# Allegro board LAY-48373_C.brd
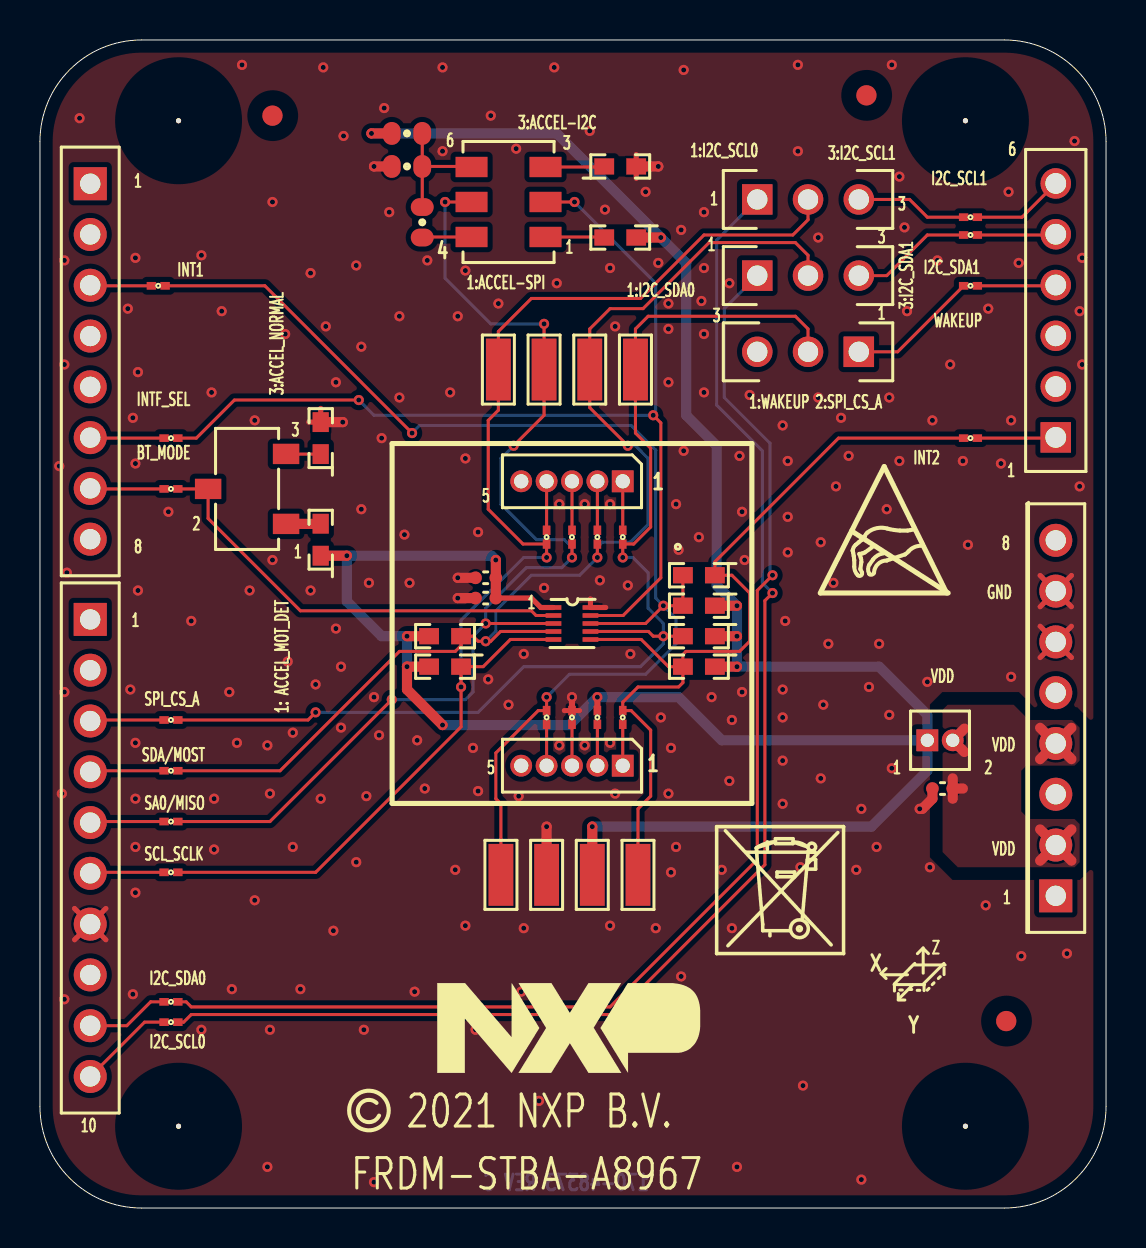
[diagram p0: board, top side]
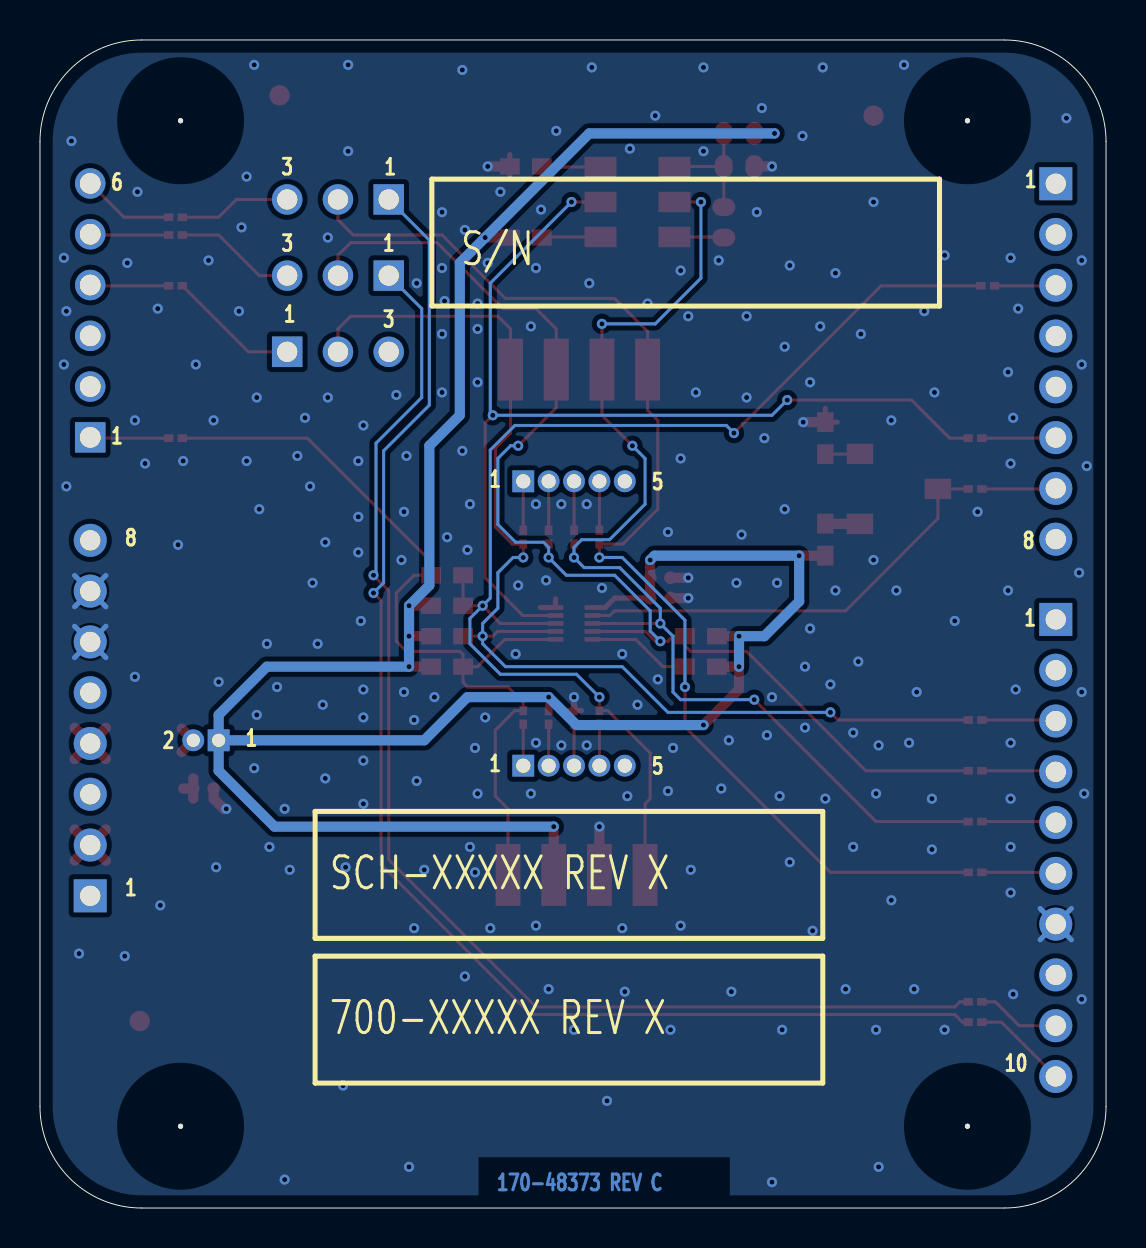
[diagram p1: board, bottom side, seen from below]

Outline 53.34 x 58.42 mm; copper layers: TOP, BOTTOM. Coordinates in mm from the lower left corner of the outline.
Outline path: 0,53.34 0,5.08 arc(1.49,1.49) 5.08,0 48.26,0 arc(51.85,1.49) 53.34,5.08 53.34,53.34 arc(51.85,56.93) 48.26,58.42 5.08,58.42 arc(1.49,56.93) 0,53.34

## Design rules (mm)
constraint set DEFAULT: min track width 0.152

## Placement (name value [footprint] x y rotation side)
C4  0.1UF  [CC0402_25]  22.3 30.51 180 top
C5  1.0UF  [CC0402_25]  22.3 31.52 180 top
C16  2.2UF  [CC0402_25]  45.16 20.98 180 top
GND  0805  [TESTPOINT_122X049MIL]  25.35 16.66 90 top
INT1  0805  [TESTPOINT_122X049MIL]  23.06 16.66 90 top
INT2  0805  [TESTPOINT_122X049MIL]  29.92 16.66 90 top
J1  HDR 1X5  [HDR1X5_50_TH]  29.16 36.35 0 top
J2  HDR 1X5  [HDR1X5_50_TH]  29.16 22.12 0 top
J3  SKT_1X8  [CON_SKT1X8_TH]  2.51 51.23 0 top
J4  SKT_1X6  [CON_SKT1X6_TH]  50.83 38.54 180 top
J5  SKT_1X10  [CON_SKT1X10_TH]  2.51 29.44 0 top
J6  SKT_1X8  [CON_SKT1X8_TH]  50.83 15.61 180 top
J7  HDR TH 1X3  [HDR103]  35.89 46.63 90 top
J8  HDR TH 1X3  [HDR103]  35.89 50.44 90 top
J9  HDR TH 1X3  [HDR103]  40.97 42.82 270 top
J10  HDR 1X2  [HDR1X2_1P27_TH]  44.4 23.39 180 top
NOREF  -  [unnamed]  6.93 54.38 0 top
NOREF#2  -  [#2]  46.48 0 90 top
NOREF#3  -  [#2]  -125.2 -12.08 90 top
NOREF#4  -  [#2]  30.55 15.66 90 top
NOREF#5  -  [#2]  23.69 15.66 90 top
NOREF#6  -  [#2]  -142.22 4.41 0 top
NOREF#7  -  [#2]  25.85 40.94 90 top
NOREF#8  -  [unnamed]  41.35 55.65 180 top
NOREF#9  -  [#2]  -125.2 3.16 90 top
NOREF#10  -  [#2]  33.86 12.73 0 top
NOREF#11  -  [#2]  -131.4 5.34 0 top
NOREF#12  -  [#2]  -125.2 -1.92 90 top
NOREF#13  -  [#2]  16.46 4.85 0 top
NOREF#14  -  [#2]  -142.22 1.87 0 top
NOREF#15  -  [#2]  16.71 35.2 0 top
NOREF#16  -  [#2]  -125.2 4.41 0 top
NOREF#17  -  [#2]  -125.2 -8.29 0 top
NOREF#18  -  [#2]  -125.2 6.95 0 top
NOREF#19  -  [#2]  39.07 30.76 0 top
NOREF#20  -  [#2]  -142.22 -1.92 90 top
NOREF#21  -  [#2]  -134.38 2.34 0 top
NOREF#22  -  [#2]  -125.2 -13.37 0 top
NOREF#23  -  [#2]  -142.22 6.95 0 top
NOREF#24  -  [#2]  -25.42 -46.55 0 top
NOREF#25  -  [#2]  29.3 17.66 0 top
NOREF#26  -  [#2]  -431.98 245.39 0 top
NOREF#27  -  [#2]  24.6 42.94 0 top
NOREF#28  -  [#2]  27.01 15.66 90 top
NOREF#29  -  [unnamed]  46.3 54.38 0 top
NOREF#30  -  [#2]  16.71 20.98 90 top
NOREF#31  -  [#2]  -142.22 3.16 90 top
NOREF#32  -  [#2]  -125.2 5.7 90 top
NOREF#33  -  [#2]  -142.22 5.7 90 top
NOREF#34  -  [#2]  -142.22 -14.62 90 top
NOREF#35  -  [unnamed]  6.93 4.09 0 top
NOREF#36  -  [#2]  -142.22 -9.54 90 top
NOREF#37  -  [#2]  -125.2 -5.75 0 top
NOREF#38  -  [#2]  16.71 20.98 0 top
NOREF#39  -  [#2]  27.01 15.66 0 top
NOREF#40  -  [#2]  -125.2 -9.54 90 top
NOREF#41  -  [#2]  52.79 55.63 0 top
NOREF#42  -  [#2]  22.44 17.66 0 top
NOREF#43  -  [unnamed]  11.63 54.64 180 top
NOREF#44  -  [#2]  22.31 42.94 0 top
NOREF#45  -  [#2]  44.05 7.77 0 top
NOREF#46  -  [#2]  -142.22 0.62 90 top
NOREF#47  -  [#2]  -132.38 2.56 90 top
NOREF#48  -  [#2]  23.56 40.94 90 top
NOREF#49  -  [#2]  -125.2 -4.46 90 top
NOREF#50  -  [#2]  -142.22 -10.83 0 top
NOREF#51  -  [#2]  -133.38 2.56 90 top
NOREF#52  -  [#2]  -131.38 2.34 90 top
NOREF#53  -  [#2]  -142.22 -7 90 top
NOREF#54  -  [#2]  -142.22 -8.29 0 top
NOREF#55  -  [#2]  -131.61 2.84 90 top
NOREF#56  -  [#2]  -125.2 1.87 0 top
NOREF#57  -  [#2]  25.97 15.66 90 top
NOREF#58  -  [#2]  30.42 40.94 90 top
NOREF#59  -  [unnamed]  46.3 4.09 0 top
NOREF#60  -  [#2]  24.72 17.66 0 top
NOREF#61  -  [#2]  17.62 38.24 0 top
NOREF#62  -  [unnamed]  48.35 9.35 180 top
NOREF#63  -  [#2]  27.89 22.12 0 top
NOREF#64  -  [#2]  -125.2 -0.67 0 top
NOREF#65  -  [#2]  -131.61 2.84 90 top
NOREF#66  -  [#2]  -142.22 -4.46 90 top
NOREF#67  -  [#2]  -134.16 2.84 0 top
NOREF#68  -  [#2]  -125.2 -3.21 0 top
NOREF#69  -  [#2]  -142.22 -12.08 90 top
NOREF#70  -  [#2]  -142.22 -0.67 0 top
NOREF#71  -  [#2]  16.71 35.2 90 top
NOREF#72  -  [#2]  44.4 23.39 0 top
NOREF#73  -  [#2]  -142.22 -3.21 0 top
NOREF#74  -  [#2]  -142.22 -5.75 0 top
NOREF#75  -  [#2]  17.62 20.24 90 top
NOREF#76  -  [#2]  -125.2 -10.83 0 top
NOREF#77  -  [#2]  29.17 42.94 0 top
NOREF#78  -  [#2]  6.45 2.61 0 top
NOREF#79  -  [#2]  -133.38 2.56 0 top
NOREF#80  -  [#2]  -458.69 -278.74 0 top
NOREF#81  -  [#2]  26.88 42.94 0 top
NOREF#82  -  [#2]  27.89 36.35 0 top
NOREF#83  -  [#2]  -125.2 -14.62 90 top
NOREF#84  -  [#2]  0 52.62 0 top
NOREF#85  -  [#2]  -125.2 -7 90 top
NOREF#86  -  [#2]  28.13 40.94 90 top
NOREF#87  -  [#2]  43.74 24.68 0 top
NOREF#88  -  [#2]  -131.61 2.84 90 top
NOREF#89  -  [#2]  19.89 6.76 0 top
NOREF#90  -  [#2]  -125.2 0.62 90 top
NOREF#91  -  [#2]  -142.22 -13.37 0 top
NOREF#92  -  [#2]  39.57 6.25 180 bottom
NOREF#93  -  [#2]  39.57 13.49 180 bottom
NOREF#94  -  [#2]  33.73 45.11 180 bottom
R1  4.7K  [RC0603]  20.27 27.08 180 top
R3  4.7K  [RC0603]  20.27 28.6 180 top
R4  10K  [RC0603]  32.97 28.6 180 top
R6  10K  [RC0603]  32.97 30.12 180 top
R8  100K  [RC0603_OV]  18.36 52.1 180 top
R9  10K  [RC0603]  32.97 27.08 180 top
R10  0  [RC0603]  32.97 31.65 180 top
R12  100K  [RC0603_OV]  18.36 53.75 0 top
R19  10K  [RC0603]  14.05 38.51 90 top
R20  10K  [RC0603]  14.05 33.43 90 top
R21  10K  [RC0603]  29.03 52.1 0 top
R24  10K  [RC0603]  29.03 48.54 180 top
R28  0  [RC0603_OV]  19.13 49.3 90 top
SA0_MISO  0805  [TESTPOINT_122X049MIL]  25.22 41.94 90 top
SCL1_SCLK  0805  [TESTPOINT_122X049MIL]  22.94 41.94 90 top
SDA1_MOSI  0805  [TESTPOINT_122X049MIL]  27.51 41.94 90 top
SH1  0  [SH0201]  25.35 24.54 90 top
SH4  0  [SH0201]  27.89 24.54 90 top
SH5  0  [SH0201]  25.35 33.55 270 top
SH8  0  [SH0201]  29.16 33.55 270 top
SH9  0  [SH0201]  27.89 33.55 270 top
SH10  0  [SH0201]  29.16 24.54 90 top
SH11  0  [SH0201]  26.62 33.55 270 top
SH20  0  [SH0201]  26.62 24.54 90 top
SH21  0  [SH0201]  46.56 49.56 0 top
SH22  0  [SH0201]  5.92 46.13 0 top
SH23  0  [SH0201]  46.56 48.67 0 top
SH27  0  [SH0201]  46.56 38.51 0 top
SH30  0  [SH0201]  6.55 24.41 0 top
SH31  0  [SH0201]  6.55 21.87 0 top
SH32  0  [SH0201]  6.55 19.33 0 top
SH33  0  [SH0201]  6.55 16.79 0 top
SH34  0  [SH0201]  6.55 10.31 0 top
SH35  0  [SH0201]  6.55 9.3 0 top
SH37  0  [SH0201]  6.55 38.51 0 top
SH38  0  [SH0201]  6.55 35.97 0 top
SH39  0  [SH0201]  46.56 46.13 0 top
SPI_CS_A  0805  [TESTPOINT_122X049MIL]  29.79 41.94 90 top
SW1  CAS-120TB  [SW3_1P75_3X6]  10.36 35.97 90 top
SW2  CAS-220TA  [SW6_1P75_4X5]  23.44 50.32 90 top
U2  FXLS8967AFR3  [DFN_10_0P4_2X2]  26.62 29.24 0 top
VDD  0805  [TESTPOINT_122X049MIL]  27.64 16.66 270 top

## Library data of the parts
C4 C5 C16 = CAP_NP
GND INT1 INT2 SA0_MISO SCL1_SCLK SDA1_MOSI SPI_CS_A VDD = TEST_POINT
J1 J2 = CONN_HDR_5X1
J3 J6 = CONN_HDR_8X1
J4 = CONN_HDR_6X1
J5 = CONN_HDR_10X1
J7-J9 = CONN_HDR_3X1
J10 = CONN_HDR_2X1
R1 R3 R4 R6 R8-R10 R12 R19-R21 R24 R28 = RES
SH1 SH4 SH5 SH8-SH11 SH20-SH23 SH27 SH30-SH35 SH37-SH39 = RES_SHORT-2: Tolerance: TOLERANCE; User Part Number: 470-76473
SW1 = SW3_SPDT_SLD
SW2 = SW_SL_DPDT_6P
U2 = FXLS8962AF_DFN10

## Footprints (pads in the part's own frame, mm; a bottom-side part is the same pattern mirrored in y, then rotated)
CC0402_25
  round 0.635 smd: 1(-0.508,0) 2(0.508,0)
CON_SKT1X6_TH
  rect 1.524x1.524 hole 1.041: 1(0,0)
  round 1.524 hole 1.041: 2(0,-2.54) 3(0,-5.08) 4(0,-7.62) 5(0,-10.16) 6(0,-12.7)
CON_SKT1X8_TH
  rect 1.651x1.651 hole 1.016: 1(0,0)
  round 1.651 hole 1.016: 2(0,-2.54) 3(0,-5.08) 4(0,-7.62) 5(0,-10.16) 6(0,-12.7) 7(0,-15.24) 8(0,-17.78)
CON_SKT1X10_TH
  rect 1.651x1.651 hole 1.016: 1(0,0)
  round 1.651 hole 1.016: 2(0,-2.54) 3(0,-5.08) 4(0,-7.62) 5(0,-10.16) 6(0,-12.7) 7(0,-15.24) 8(0,-17.78) 9(0,-20.32) 10(0,-22.86)
DFN_10_0P4_2X2
  rect 0.787x0.229 smd: 1(-0.925,0.8) 2(-0.925,0.4) 3(-0.925,0) 4(-0.925,-0.4) 5(-0.925,-0.8) 6(0.925,-0.8) 7(0.925,-0.4) 8(0.925,0) 9(0.925,0.4) 10(0.925,0.8)
HDR1X2_1P27_TH
  rect 1.092x1.092 hole 0.66: 1(0,0)
  round 1.092 hole 0.66: 2(-1.27,0)
HDR1X5_50_TH
  rect 1.092x1.092 hole 0.711: 1(0,0)
  round 1.092 hole 0.711: 2(-1.27,0) 3(-2.54,0) 4(-3.81,0) 5(-5.08,0)
HDR103
  rect 1.524x1.524 hole 1.016: 1(0,0)
  round 1.524 hole 1.016: 2(0,-2.54) 3(0,-5.08)
RC0603
  rect 0.991x0.813 smd: 1(-0.8,0) 2(0.8,0)
RC0603_OV
  oval 0.889x1.143 smd: 1(-0.762,0) 2(0.762,0)
SH0201
  rect 0.47x0.381 smd: 1(-0.343,0) 2(0.343,0)
SW3_1P75_3X6
  rect 1.016x1.321 smd: 1(-1.75,-1.95) 2(0,1.95) 3(1.75,-1.95)
SW6_1P75_4X5
  rect 1.016x1.6 smd: 1(-1.75,-1.85) 2(0,-1.85) 3(1.75,-1.85) 4(-1.75,1.85) 5(0,1.85) 6(1.75,1.85)
TESTPOINT_122X049MIL
  rect 3.099x1.245 smd: 1(0,0)
unnamed
  round 0.254 hole 3.175 unplated: (0,0)

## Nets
GND: C4.2 C5.2 C16.2 GND.1 J5.7 J6.6 J6.7 R8.2 R19.2 R21.2 SH20.2 U2.10
VDD: C4.1 C5.1 J10.1 R1.2 R3.2 R4.1 R6.1 R9.1 R12.1 R20.1 R24.1 SH4.2 U2.1(VDD) VDD.1
BT_MODE: SH38.2 SW1.2 U2.2
I2C_SCL0: J8.1 SH35.2
I2C_SCL1: J8.3 SH21.1
I2C_SDA0: J7.1 SH34.2
I2C_SDA1: J7.3 SH23.1
INT1: INT1.1 R6.2 R10.2 SH1.2 SH22.2 U2.8
INT2: INT2.1 R9.2 R10.1 SH10.2 SH27.1 U2.6
INTF_SEL: SH37.2 SW2.2 U2.9
SA0_MISO: SA0_MISO.1 SH11.2 SH32.2 SW2.5(COM2) U2.3
SCL1_SCLK: J8.2 R1.1 SCL1_SCLK.1 SH5.2 SH33.2 U2.5
SDA1_MOSI: J7.2 R3.1 SDA1_MOSI.1 SH9.2 SH31.2 U2.4
SPI_CS_A: J9.2 R4.2 SH8.2 SH30.2 SPI_CS_A.1 U2.7
WAKEUP: J9.1 SH39.1
N00622: J5.9 SH34.1
N00628: J5.10 SH35.1
N00993: C16.1 J6.2 J6.4 J10.2
N05692: J4.6 SH21.2
N05729: J4.5 SH23.2
N16652859: J5.4 SH31.1
N16652885: J5.5 SH32.1
N16652889: J5.6 SH33.1
N16653001: J5.3 SH30.1
N16659634: J4.1 SH27.2
N16701284: J3.3 SH22.1
N16711839: J2.1 SH10.1
N16711841: J2.2 SH4.1
N16711843: J2.3 SH20.1
N16711845: J2.4 SH1.1
N16711871: J1.1 SH8.1
N16711873: J1.2 SH9.1
N16711875: J1.3 SH11.1
N16711877: J1.4 SH5.1
N16715705: R20.2 SW1.1
N16718521: R21.1 SW2.3
N16718681: R24.2 SW2.1
N16719014: R8.1 R12.2 R28.2 SW2.6
N16719865: R28.1 SW2.4
N16720544: J3.6 SH37.1
N16720548: J3.7 SH38.1
N16721741: J4.4 SH39.2
N16884640: R19.1 SW1.3

Pads without a net: J1 5; J2 5; J3 1 2 4 5 8; J4 2 3; J5 1 2 8; J6 1 3 5 8; J9 3

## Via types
v1: diameter 0.508, hole 0.254, TOP to BOTTOM, 257 vias

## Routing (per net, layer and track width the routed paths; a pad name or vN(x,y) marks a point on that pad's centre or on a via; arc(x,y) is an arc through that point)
GND: length 40.3
  TOP w0.254: J5.7 3.3,13.42 ; J5.7 1.73,13.42 ; J5.7 3.3,14.98 ; J5.7 1.73,14.98 ; 27,24.88 SH20.2 26.24,24.88 ; 29.83,52.69 R21.2 29.83,51.5 ; 13.45,39.31 R19.2 14.05,39.99 ; 27.54,30.47 U2.10 28.31,30.04 ; 50.04,27.53 J6.6 ; J6.6 50.04,29.1 ; J6.6 51.61,29.1 ; J6.6 51.61,27.53 ; J6.7 51.61,30.07 ; J6.7 51.61,31.64 ; J6.7 50.04,30.07 ; J6.7 50.04,31.64
  TOP w0.305: SH20.2 v1(26.62,25.55)
  TOP w0.508: R21.2 v1(30.94,52.1) ; v1(44.02,19.96) 44.15,19.96 44.65,20.47 C16.2 ; GND.1 v1(25.35,19.08) ; 17.6,52.1 v1(16.71,52.1) ; R19.2 v1(15.15,39.31) ; C5.2 v1(20.9,31.52) ; C4.2 v1(20.9,30.51)
  BOTTOM w0.254: J6.7 51.61,31.64 ; J6.7 50.04,30.07 ; J6.7 51.61,30.07 ; J6.7 50.04,31.64 ; J6.6 51.61,29.1 ; J6.6 50.04,27.53 ; J6.6 51.61,27.53 ; J6.6 50.04,29.1 ; J5.7 3.3,13.42 ; J5.7 1.73,13.42 ; J5.7 1.73,14.98 ; J5.7 3.3,14.98
  vias: v1(0.97,37.11) v1(1.09,20.73) v1(1.22,47.4) v1(1.22,42.19) v1(1.22,25.81) v1(1.22,10.44) v1(1.35,31.78) v1(1.98,54.51) v1(4.39,44.98) v1(4.52,25.93) v1(4.65,39.52) v1(4.65,10.69) v1(4.78,47.52) v1(4.78,37.24) v1(4.78,23.27) v1(4.78,20.47) v1(4.78,18.06) v1(4.78,15.77) v1(4.9,41.81) v1(4.9,30.89) v1(6.43,34.82) v1(7.57,29.36) v1(8.08,47.65) v1(8.08,8.92) v1(8.59,40.79) v1(8.71,20.47) v1(8.71,17.93) v1(9.09,44.86) v1(9.47,25.81) v1(9.6,10.95) v1(9.86,23.27) v1(10.11,57.18) v1(10.49,30.89) v1(10.74,39.4) v1(10.74,15.39) v1(11.38,23.14) v1(11.38,2.06) v1(11.51,20.73) v1(11.51,8.92) v1(11.63,50.32) v1(11.63,32.41) v1(12.27,43.71) v1(12.4,27.33) v1(12.65,23.77) v1(12.65,18.06) v1(13.03,10.95) v1(13.54,46.76) v1(13.54,30.89) v1(13.79,26.19) v1(14.05,20.47) v1(14.17,57.05) v1(14.3,44.09) v1(14.68,13.87) v1(14.81,41.3) v1(14.81,28.98) v1(15.06,27.08) v1(15.06,24.03) v1(15.19,53.62) v1(15.82,47.14) v1(15.82,17.3) v1(16.08,43.08) v1(16.08,34.95) v1(16.21,8.92) v1(16.33,20.6) v1(16.46,31.27) v1(16.71,25.55) v1(16.71,1.3) v1(16.97,23.65) v1(17.09,38.51) v1(17.22,55.02) v1(17.48,49.81) v1(17.98,44.6) v1(17.98,40.54) v1(18.24,33.68) v1(18.49,31.27) v1(18.75,10.82) v1(18.87,23.39) v1(19.25,20.98) v1(19.38,47.4) v1(20.14,57.05) v1(20.14,52.86) v1(20.52,40.79) v1(20.78,16.92) v1(20.9,44.6) v1(21.29,46.89) v1(21.29,37.49) v1(21.29,14.12) v1(21.67,23.01) v1(21.79,8.92) v1(21.92,33.81) v1(21.92,20.85) v1(22.43,26.44) v1(22.56,54.64) v1(22.94,45.24) v1(23.44,25.17) v1(23.83,52.98) v1(23.95,20.6) v1(24.08,10.82) v1(24.21,27.71) v1(24.21,14) v1(24.97,5.36) v1(25.22,31.01) v1(25.73,57.05) v1(25.86,46.25) v1(25.98,35.2) v1(25.98,23.14) v1(26.62,8.92) v1(27.25,35.2) v1(27.25,23.14) v1(27.51,53.87) v1(27.89,10.95) v1(28.02,31.39) v1(28.27,49.94) v1(28.52,47.02) v1(28.52,35.2) v1(28.52,23.27) v1(28.52,14.12) v1(28.78,44.09) v1(28.78,20.73) v1(29.41,31.14) v1(29.54,27.71) v1(30.3,50.83) v1(30.81,14) v1(30.94,47.27) v1(31.06,24.54) v1(31.45,45.24) v1(31.45,43.97) v1(31.45,41.3) v1(31.45,20.73) v1(31.57,23.01) v1(31.57,16.79) v1(31.83,35.2) v1(31.83,18.06) v1(31.95,32.92) v1(32.08,48.92) v1(32.08,11.58) v1(32.21,56.92) v1(32.21,37.87) v1(32.97,33.55) v1(33.1,45.36) v1(33.22,49.81) v1(33.22,47.02) v1(33.22,43.71) v1(33.22,40.79) v1(33.6,25.55) v1(34.11,16.92) v1(34.49,46.25) v1(34.49,21.36) v1(34.62,24.41) v1(34.62,14) v1(34.87,2.06) v1(35,37.62) v1(35.13,34.82) v1(35.13,25.81) v1(35.26,32.41) v1(35.51,40.67) v1(37.16,39.14) v1(37.16,25.93) v1(37.16,24.54) v1(37.16,22.38) v1(37.16,20.22) v1(37.29,29.36) v1(37.41,37.36) v1(37.41,34.57) v1(37.41,32.79) v1(37.92,57.18) v1(37.92,52.86) v1(38.05,17.04) v1(38.18,6.12) v1(38.94,48.54) v1(38.94,40.54) v1(39.07,33.3) v1(39.07,21.49) v1(39.19,25.17) v1(39.45,28.22) v1(39.7,31.27) v1(39.83,36.09) v1(40.08,39.52) v1(40.46,37.62) v1(40.84,16.92) v1(41.1,19.96) v1(41.1,1.42) v1(41.48,26.06) v1(41.86,18.06) v1(41.99,28.22) v1(42.37,34.95) v1(42.49,40.54) v1(42.49,24.66) v1(42.62,57.18) v1(42.62,22) v1(43,51.59) v1(43,37.36) v1(43.26,49.05) v1(43.38,44.86) v1(44.4,26.31) v1(44.53,17.04) v1(44.65,39.4) v1(44.91,47.4) v1(45.54,42.19) v1(46.18,37.36) v1(46.43,33.17) v1(47.32,15.14) v1(47.45,44.98) v1(48.08,37.24) v1(48.46,50.83) v1(48.59,39.4) v1(48.59,26.57) v1(48.97,47.27) v1(49.1,12.6) v1(51.38,12.73) v1(51.77,53.37) v1(52.02,44.86) v1(52.02,36.09) v1(52.15,47.52) v1(52.15,42.19)
VDD: length 132.5
  TOP w0.254: C4.1 24.59,30.51 25.06,30.04 U2.1
  TOP w0.305: SH4.2 v1(27.89,25.55)
  TOP w0.508: 19.47,28.6 v1(18.36,28.6) ; v1(22.81,32.41) C5.1 C4.1 ; 17.6,53.75 v1(16.59,53.75) ; R6.1 v1(34.87,30.12) ; R1.2 v1(18.36,27.08) 18.36,25.93 v1(20.14,24.16) ; R20.1 v1(15.35,32.63) ; R9.1 v1(34.87,27.08) ; R4.1 v1(34.87,28.6) ; R24.1 v1(31.06,48.54) ; VDD.1 v1(27.64,19.08)
  BOTTOM w0.508: J10.1 44.4,24.66 41.99,27.08 v1(34.87,27.08) v1(34.87,28.6) v1(34.87,30.12) 33.86,31.14 33.86,38.13 32.33,39.65 32.33,47.27 v1(31.06,48.54) 25.86,53.75 v1(16.59,53.75) ; J10.1 44.4,21.87 41.61,19.08 v1(27.64,19.08) ; J10.1 34.11,23.39 31.95,25.55 v1(27.89,25.55) 26.49,24.16 v1(20.14,24.16) ; v1(18.36,27.08) v1(18.36,28.6) 17.09,28.6 15.35,30.34 v1(15.35,32.63) 22.59,32.63 v1(22.81,32.41)
BT_MODE: length 22.3
  TOP w0.152: U2.2 24.82,29.64 24.59,29.87 13.03,29.87 8.41,34.49 SW1.2 SH38.2
I2C_SCL0: length 68.1
  TOP w0.152: SH35.2 7.19,9.3 7.57,9.68 28.78,9.68 36.27,17.17 36.27,30.38 v1(36.65,30.76)
  BOTTOM w0.152: v1(36.65,30.76) 36.14,31.27 36.14,37.87 33.86,40.16 33.86,48.41 J8.1
I2C_SCL1: length 5.6
  TOP w0.152: J8.3 43.51,50.44 44.4,49.56 SH21.1
I2C_SDA0: length 63.4
  TOP w0.152: v1(36.65,31.65) 35.89,30.89 35.89,17.42 28.52,10.06 7.57,10.06 7.32,10.31 SH34.2
  BOTTOM w0.152: J7.1 34.24,44.98 34.24,40.54 36.53,38.25 36.53,31.78 v1(36.65,31.65)
I2C_SDA1: length 6.1
  TOP w0.152: J7.3 42.37,46.63 44.4,48.67 SH23.1
INT1: length 62.8
  TOP w0.152: SH22.2 11.25,46.13 v1(18.62,38.76) ; U2.8 30.3,29.24 v1(31.19,30.12) 32.17,30.12 R10.2 ; INT1.1 23.06,20.22 22.81,20.47 22.81,22.76 24.93,24.88 SH1.2 v1(25.35,25.55)
  BOTTOM w0.152: v1(25.35,25.55) 26.49,26.7 30.3,26.7 31.83,28.22 31.83,29.49 v1(31.19,30.12) 30.81,30.51 30.81,37.91 29.58,39.14 19,39.14 v1(18.62,38.76)
INT2: length 43.6
  TOP w0.152: U2.6 30.09,28.44 31.45,27.08 R9.2 ; R9.2 32.17,27.69 32.32,27.84 35,27.84 35.51,28.35 35.51,30.76 34.62,31.65 R10.1 33.77,32.32 39.95,38.51 SH27.1 ; R9.2 32.17,26.28 31.95,26.06 29.92,26.06 29.16,25.3 SH10.2 29.58,24.88 30.56,23.9 30.56,20.6 29.92,19.96 INT2.1
INTF_SEL: length 51.3
  TOP w0.152: v1(30.68,39.65) 31.06,39.27 31.06,31.52 29.18,29.64 U2.9 ; SW2.2 v1(26.75,50.32) ; SH37.2 7.82,38.51 9.73,40.41 v1(15.95,40.41)
  BOTTOM w0.152: v1(15.95,40.41) 16.71,39.65 v1(30.68,39.65) 30.81,39.78 30.81,46.25 v1(26.75,50.32)
SA0_MISO: length 57.2
  TOP w0.152: SW2.5 v1(20.27,50.32) ; SH11.2 v1(26.62,32.54) ; v1(22.3,29.24) U2.3 ; v1(25.22,44.22) SA0_MISO.1 25.22,39.65 v1(23.7,38.13) ; v1(17.6,25.43) 11.51,19.33 SH32.2
  BOTTOM w0.152: v1(25.22,44.22) 22.56,44.22 20.27,46.51 v1(20.27,50.32) ; v1(17.6,25.43) 21.29,25.43 21.67,25.81 21.67,28.6 v1(22.3,29.24) 22.3,30 24.33,32.03 26.11,32.03 v1(26.62,32.54) 26.62,33.05 26.24,33.43 24.84,33.43 23.06,35.2 23.06,37.49 v1(23.7,38.13)
SCL1_SCLK: length 66.5
  TOP w0.152: J8.2 38.43,49.43 37.67,48.67 33.22,48.67 30.05,45.49 24.59,45.49 22.94,43.84 SCL1_SCLK.1 22.94,39.9 22.43,39.4 22.43,34.95 24.17,33.21 SH5.2 v1(25.35,32.54) ; U2.5 23.53,28.44 22.17,27.08 R1.1 v1(21.07,26.06) 21.07,24.07 13.79,16.79 SH33.2
  BOTTOM w0.152: v1(25.35,32.54) 24.21,32.54 21.07,29.4 v1(21.07,26.06)
SDA1_MOSI: length 59.5
  TOP w0.152: U2.4 23.04,28.84 22.56,28.35 v1(22.3,28.35) 21.92,28.35 21.67,28.6 R3.1 21.07,28.13 20.78,27.84 17.98,27.84 12.01,21.87 SH31.2 ; v1(27.89,32.54) SH9.2 ; v1(29.41,38.13) 27.51,40.03 SDA1_MOSI.1 27.51,43.97 28.52,44.98 30.18,44.98 33.48,48.29 37.8,48.29 38.43,47.65 J7.2
  BOTTOM w0.152: v1(22.3,28.35) 22.81,28.85 22.81,29.87 24.59,31.65 27,31.65 v1(27.89,32.54) 27.89,33.05 28.14,33.3 29.54,33.3 30.43,34.19 30.43,37.49 29.79,38.13 v1(29.41,38.13)
SPI_CS_A: length 59
  TOP w0.152: 32.17,28.6 v1(31.19,28.6) 30.68,28.6 30.45,28.84 U2.7 ; SH30.2 13.41,24.41 v1(13.79,24.79) ; J9.2 38.43,43.97 37.8,44.6 30.43,44.6 29.79,43.97 SPI_CS_A.1 29.79,38.76 30.56,38 30.56,34.06 29.71,33.21 SH8.2 v1(29.16,32.54)
  BOTTOM w0.152: v1(13.79,24.79) 21.92,24.79 24.21,27.08 30.05,27.08 31.19,28.22 v1(31.19,28.6) 31.19,29.24 30.43,30 30.43,31.78 29.67,32.54 v1(29.16,32.54)
WAKEUP: length 6.6
  TOP w0.152: SH39.1 42.91,42.82 J9.1
N00622: length 4.2
  TOP w0.152: SH34.1 5.54,10.31 4.34,9.12 J5.9
N00628: length 4.8
  TOP w0.152: J5.10 5.23,9.3 SH35.1
N00993: length 12
  TOP w0.508: C16.1 45.67,21.49 ; C16.1 46.18,20.98 ; C16.1 45.67,20.47 ; 50.04,24.02 J6.4 ; J6.4 50.04,22.45 ; J6.4 51.61,24.02 ; J6.4 51.61,22.45 ; 46.25,22.81 J10.2 46.25,23.98 ; J6.2 51.61,18.94 ; J6.2 50.04,18.94 ; J6.2 50.04,17.37 ; J6.2 51.61,17.37
N05692: length 4.6
  TOP w0.152: SH21.2 49.14,49.56 J4.6
N05729: length 3.9
  TOP w0.152: J4.5 50.79,48.67 SH23.2
N16652859: length 3.7
  TOP w0.152: SH31.1 2.57,21.87 J5.4
N16652885: length 3.7
  TOP w0.152: J5.5 2.57,19.33 SH32.1
N16652889: length 3.7
  TOP w0.152: J5.6 2.57,16.79 SH33.1
N16653001: length 3.7
  TOP w0.152: J5.3 2.57,24.41 SH30.1
N16659634: length 3.9
  TOP w0.152: J4.1 50.79,38.51 SH27.2
N16701284: length 3.1
  TOP w0.152: SH22.1 2.54,46.13 J3.3
N16711839: length 2.1
  TOP w0.152: SH10.1 J2.1
N16711841: length 2.1
  TOP w0.152: SH4.1 J2.2
N16711843: length 2.1
  TOP w0.152: SH20.1 J2.3
N16711845: length 2.1
  TOP w0.152: SH1.1 J2.4
N16711871: length 2.5
  TOP w0.152: SH8.1 J1.1
N16711873: length 2.5
  TOP w0.152: SH9.1 J1.2
N16711875: length 2.5
  TOP w0.152: SH11.1 J1.3
N16711877: length 2.5
  TOP w0.152: SH5.1 J1.4
N16715705: length 1.7
  TOP w0.508: R20.2 14.04,34.22 SW1.1
N16718521: length 2.9
  TOP w0.152: SW2.3 28.2,52.07 R21.1
N16718681: length 2.9
  TOP w0.152: SW2.1 28.2,48.57 R24.2
N16719014: length 6.2
  TOP w0.152: R8.1 R28.2 ; R8.1 21.57,52.1 SW2.6 ; R8.1 R12.2
N16719865: length 2.5
  TOP w0.152: SW2.4 19.15,48.57 R28.1
N16720544: length 3.7
  TOP w0.152: J3.6 2.54,38.51 SH37.1
N16720548: length 3.7
  TOP w0.152: SH38.1 2.54,35.97 J3.7
N16721741: length 3.9
  TOP w0.152: J4.4 50.79,46.13 SH39.2
N16884640: length 1.7
  TOP w0.152: R19.1 12.32,37.71 SW1.3

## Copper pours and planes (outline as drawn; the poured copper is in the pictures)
GND on TOP: 5.08,0.64 1.94,1.94 0.64,5.08 0.64,53.34 1.94,56.48 5.08,57.78 48.26,57.78 51.4,56.48 52.7,53.34 52.7,5.08 51.4,1.94 48.26,0.64 ; 8 cut-outs
GND on BOTTOM: 5.08,0.64 1.94,1.94 0.64,5.08 0.64,53.34 1.94,56.48 5.08,57.78 48.26,57.78 51.4,56.48 52.7,53.34 52.7,5.08 51.4,1.94 48.26,0.64 ; 1 cut-out
N00993 on TOP: 45.16,24.92 45.16,17.81 45.92,17.04 51.77,17.04 52.02,17.3 52.02,19.2 51.77,19.46 49.48,19.46 49.1,19.84 49.1,21.87 49.35,22.12 51.77,22.12 52.02,22.38 52.02,24.03 51.64,24.41 49.48,24.41 48.72,25.17 45.42,25.17

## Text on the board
BOTTOM: 170-48373 REV C | 5 of 8 | L2_SS
Board Geometry/Soldermask Bottom: 6 OF 8 | SECONDARY SOLDERMASK
Ref Des/Silkscreen Bottom: 7 OF 8 | SECONDARY SILKSCREEN
User.Comments: 17 | 1 OF 1 | TEST PROBE | 1/1 | 1
TOP: 4 OF 8 | L1_PS
Board Geometry/Soldermask Top: 3 OF 8 | PRIMARY SOLDERMASK
Ref Des/Silkscreen Top: INTF_SEL | BT_MODE | SDA/MOST | SPI_CS_A | SA0/MISO | SCL_SCLK | I2C_SDA0 | I2C_SCL0 | INT1 | INT2 | I2C_SDA1 | I2C_SCL1 | Z | WAKEUP | GND | VDD | 3:ACCEL-I2C | 3:I2C_SCL1 | 3:ACCEL_NORMAL | 3:I2C_SDA1 | X | Y | 2 OF 8 | PRIMARY SILKSCREEN | FRDM-STBA-A8967
XSECTION_CHART: *  SURFACE - AIR 0 MIL | *  DIELECTRIC - DRY_FILM_MASK 0.7 MIL | L1 TOP CONDUCTOR - 1/2OZ_COPPER_PLATED_FOIL 2.1 MIL | *  DIELECTRIC - FR-4 56.4 MIL | L2 BOTTOM CONDUCTOR - 1/2OZ_COPPER_PLATED_FOIL 2.1 MIL | DESIGN CROSS SECTION CHART | ___________________________ | TOTAL THICKNESS 62 MIL | 1-2 | INTENTIONAL 21 SHORTS AT: | Location           RefDes      Net 1         Net 2 | (-815.00 665.00)   SH22      N16701284  &  INT1 | (-790.00 -785.00)  SH35      N00628     &  I2C_SCL0 | (-790.00 -745.00)  SH34      N00622     &  I2C_SDA0 | (-790.00 -490.00)  SH33      N16652889  &  SCL1_SCLK | (-790.00 -190.00)  SH30      N16653001  &  SPI_CS_A | (-790.00 -290.00)  SH31      N16652859  &  SDA1_MOSI | (-790.00 -390.00)  SH32      N16652885  &  SA0_MISO | (-790.00 365.00)   SH37      N16720544  &  INTF_SEL | (-790.00 265.00)   SH38      N16720548  &  BT_MODE | (-50.00 -185.00)   SH1       N16711845  &  INT1 | (-50.00 170.00)    SH5       N16711877  &  SCL1_SCLK | (100.00 -185.00)   SH10      N16711839  &  INT2 | (0.00 -185.00)     SH20      N16711843  &  GND | (50.00 -185.00)    SH4       N16711841  &  VDD | (50.00 170.00)     SH9       N16711873  &  SDA1_MOSI | (100.00 170.00)    SH8       N16711871  &  SPI_CS_A | (0.00 170.00)      SH11      N16711875  &  SA0_MISO | (785.00 365.00)    SH27      INT2       &  N16659634 | (785.00 665.00)    SH39      WAKEUP     &  N16721741 | (785.00 765.00)    SH23      I2C_SDA1   &  N05729 | (785.00 800.00)    SH21      I2C_SCL1   &  N05692 | 8 | 19 | 16
DIMENSION: PRIMARY DATUM GRID ORIGIN
BODY_CENTER: 1 OF 8 | PASTEMASK TOP
DISPLAY_TOP: 8 OF 8 | SECONDARY PASTEMASK
User.12: 07-02-21 | 11-10-21 | R.Y. | B | C | UPDATE PER THE LATEST SCH | UPDATE THE SENSOR PART LAYOUT
User.16: FIGURE | FINISHED_SIZE | 10.0 | 26.0 | 28.0 | 40.0 | 41.0 | 125.0 | DRILL CHART: TOP to BOTTOM | ALL UNITS ARE IN MILS | TOLERANCE_DRILL | +0.0/-10.0 | +2.0/-2.0 | +3.0/-3.0 | PLATED | NON-PLATED | QTY | 257 | 2 | 10 | 35 | 6 | 4
